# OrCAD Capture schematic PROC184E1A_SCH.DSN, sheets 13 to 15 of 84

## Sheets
13 13. SOC SERDES1 IF: size C; title: SERDES INTERFACE; company: TEXAS INSTRUMENTS INCORPORATED; note: PROC184_SCH
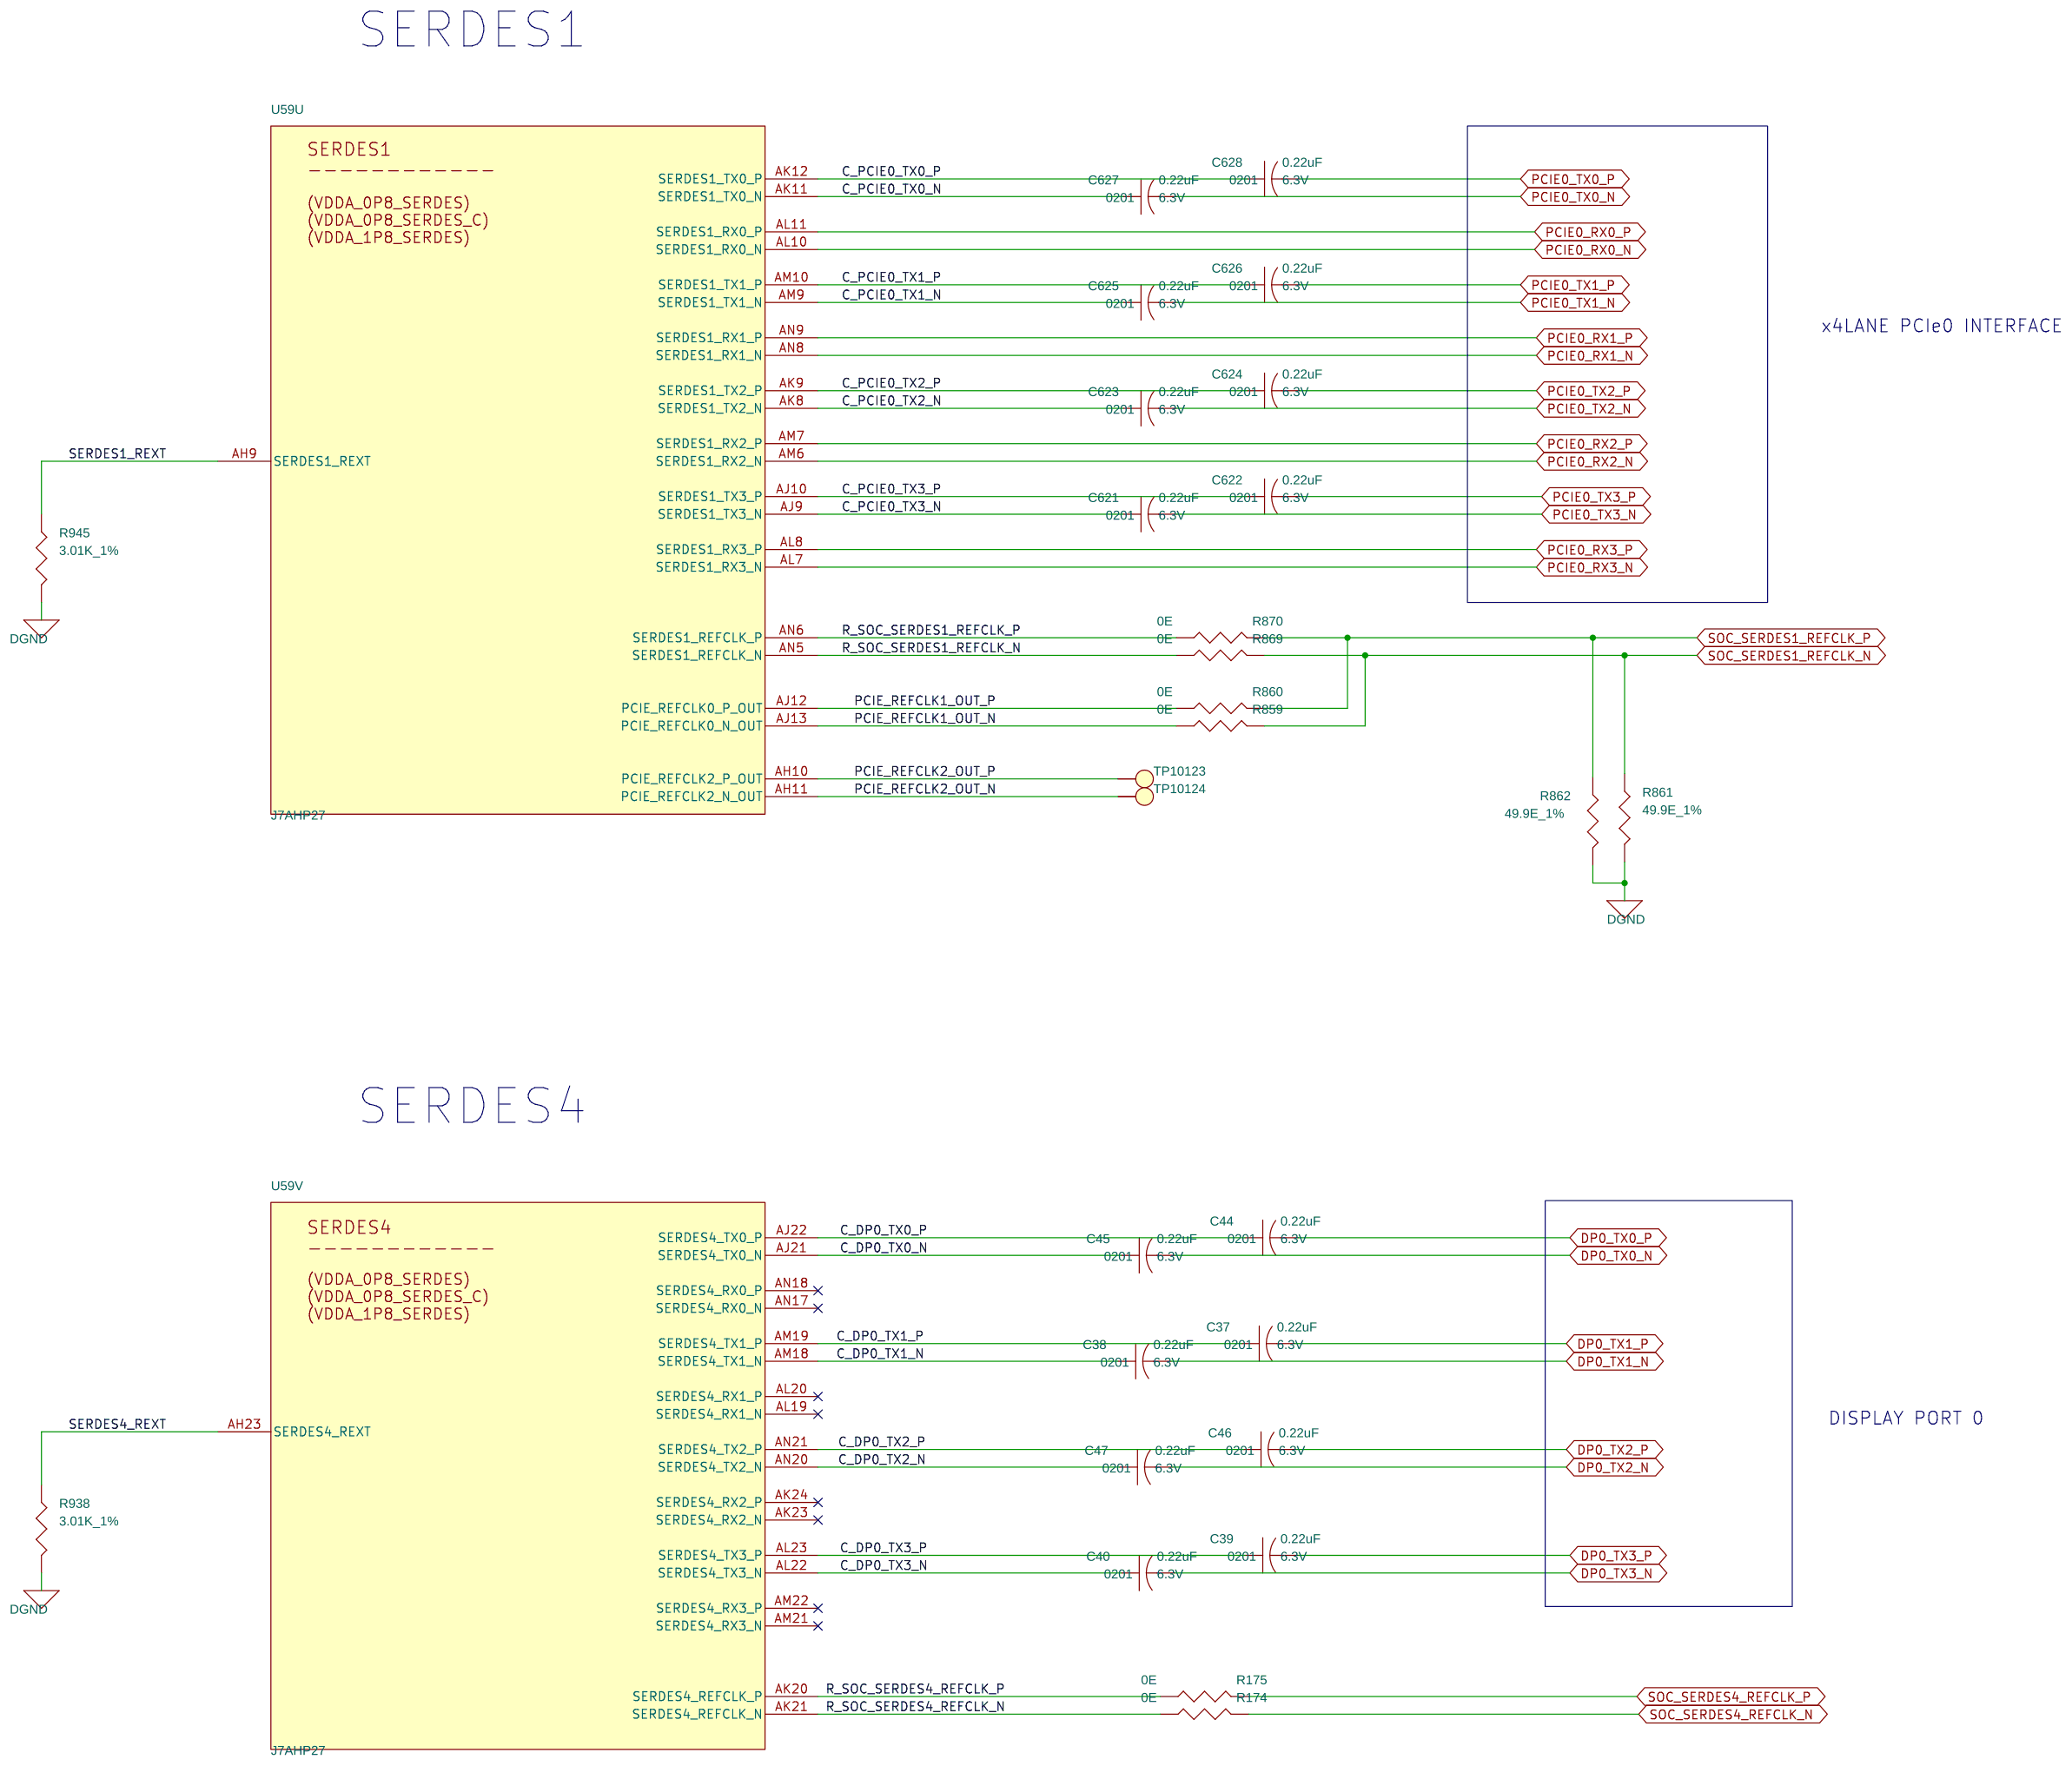
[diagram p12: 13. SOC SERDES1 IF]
14 14. SOC EMIF0 & LPDDR4: size C; title: EMIF0; company: TEXAS INSTRUMENTS INCORPORATED; note: PROC184_SCH
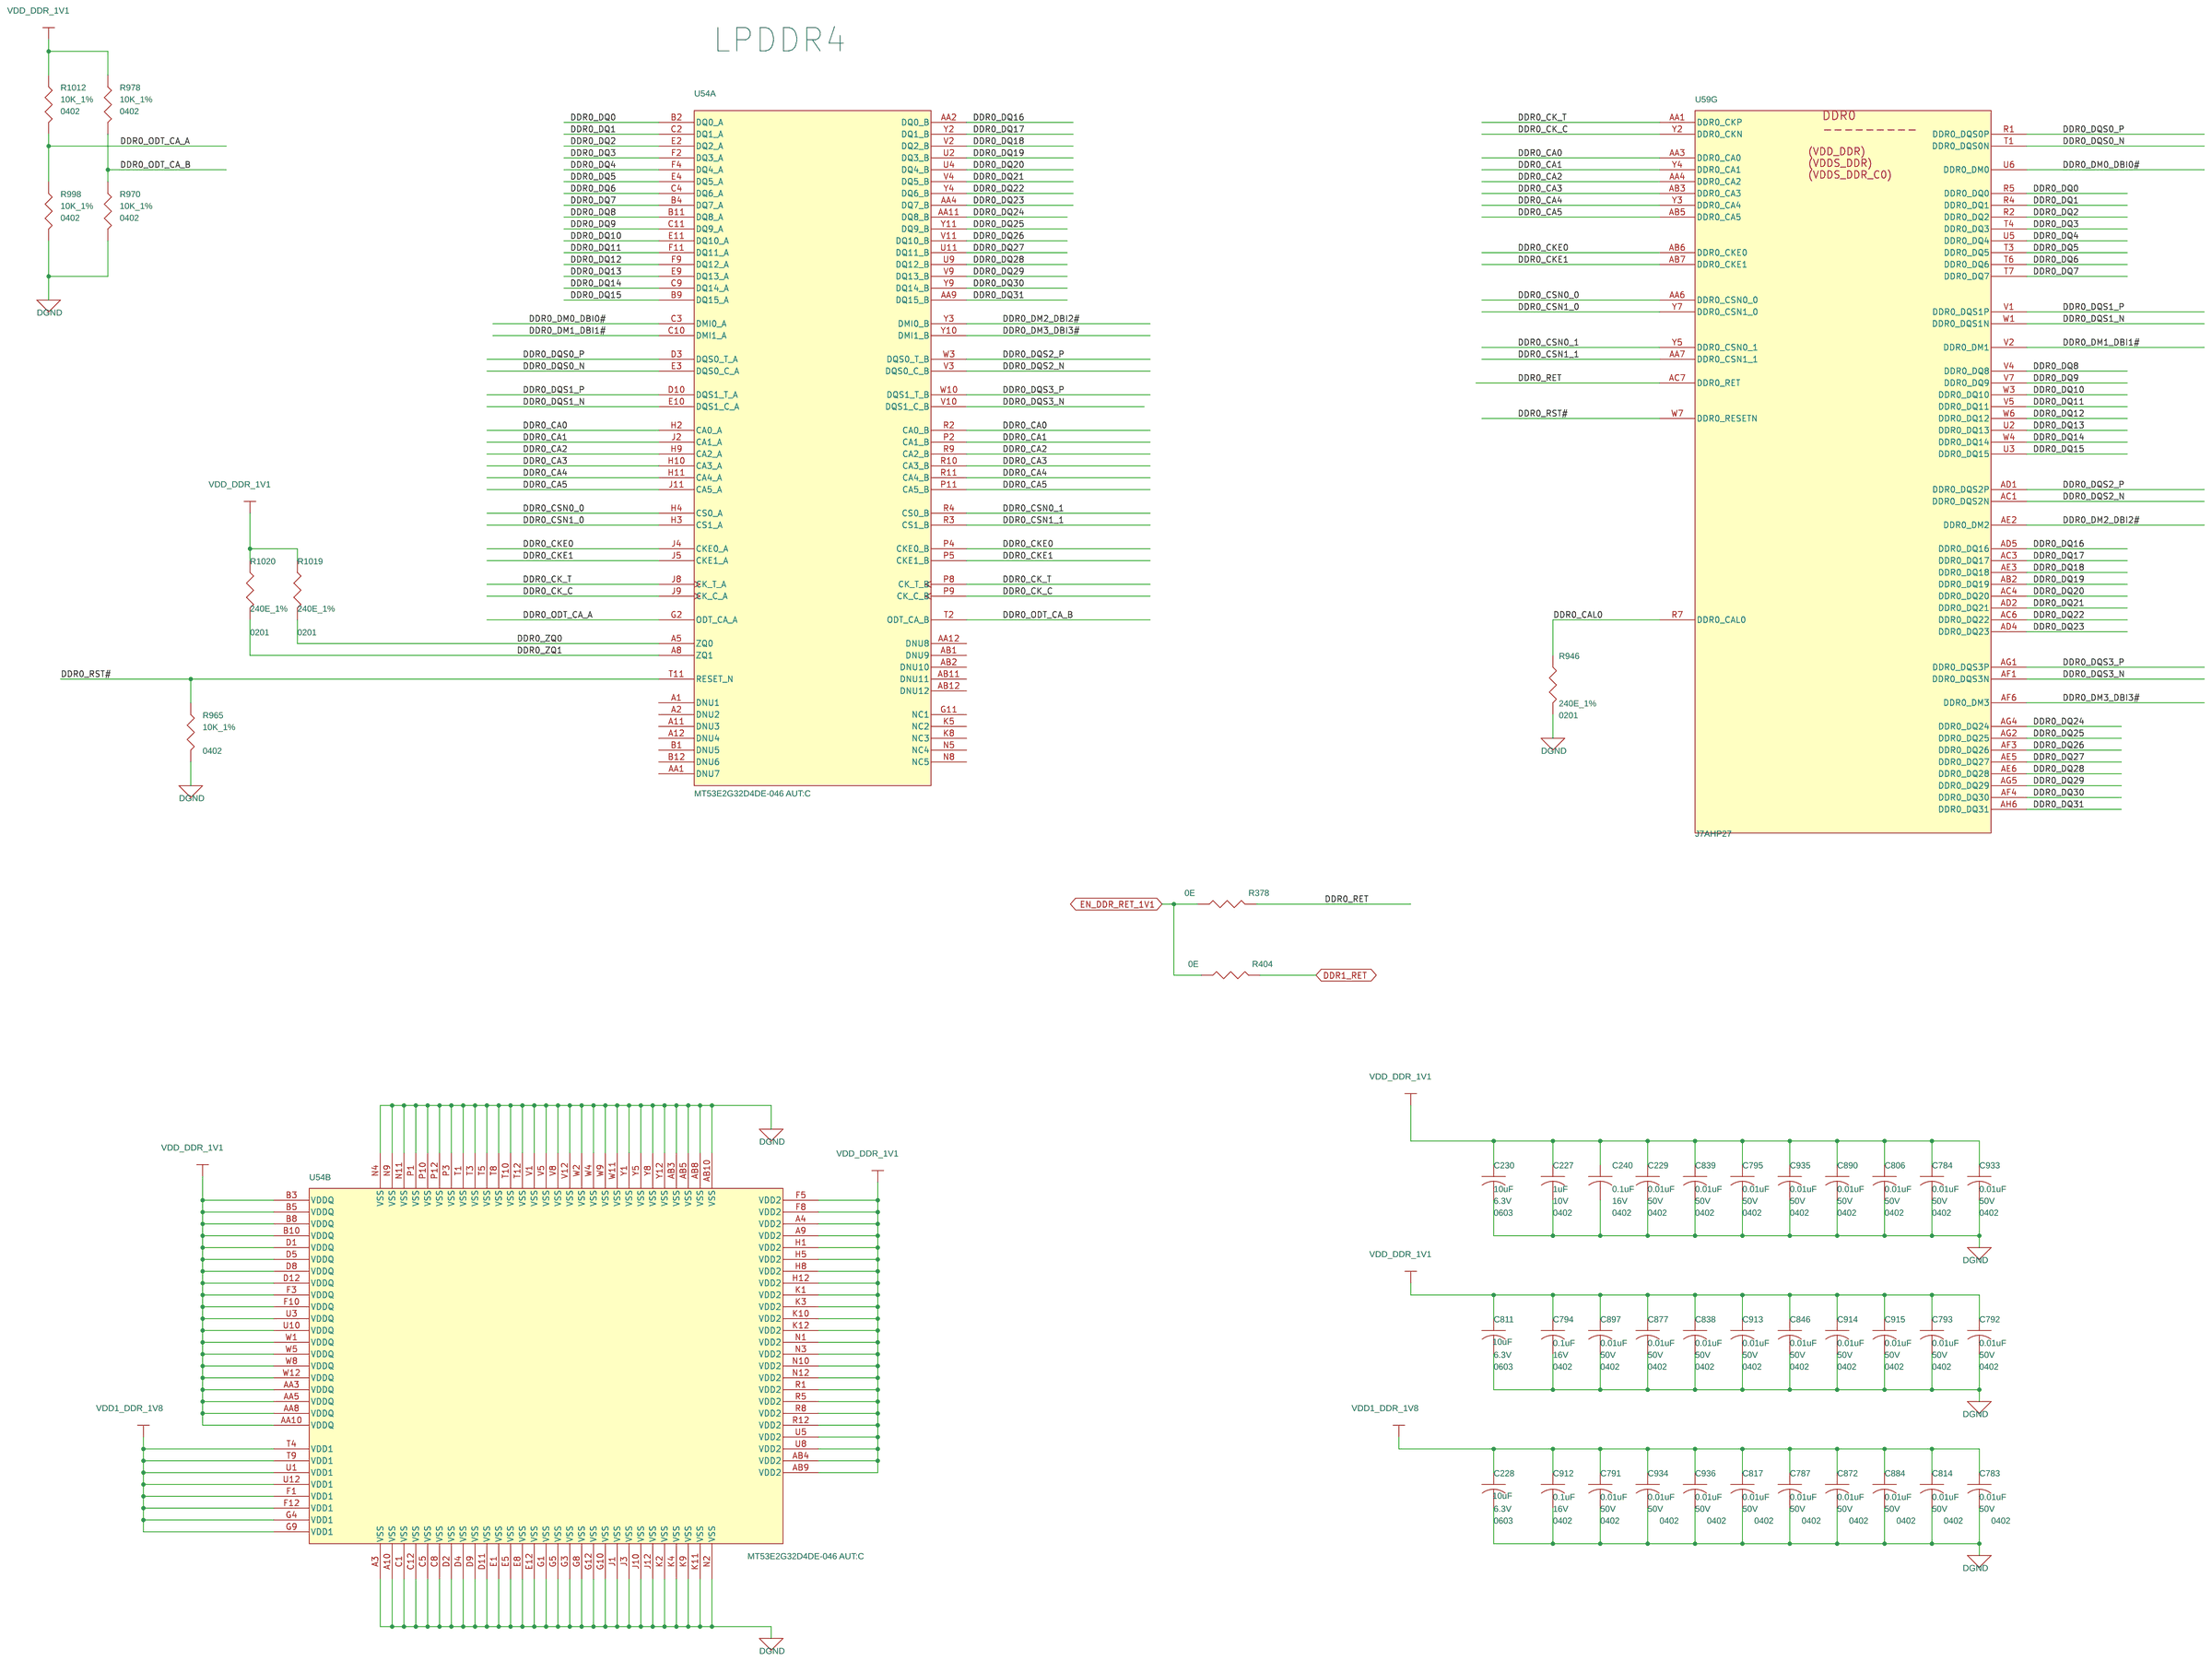
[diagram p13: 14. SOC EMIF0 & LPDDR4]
15 15. SOC EMIF1 & LPDDR4: size C; title: EMIF1; company: TEXAS INSTRUMENTS INCORPORATED; note: PROC184_SCH
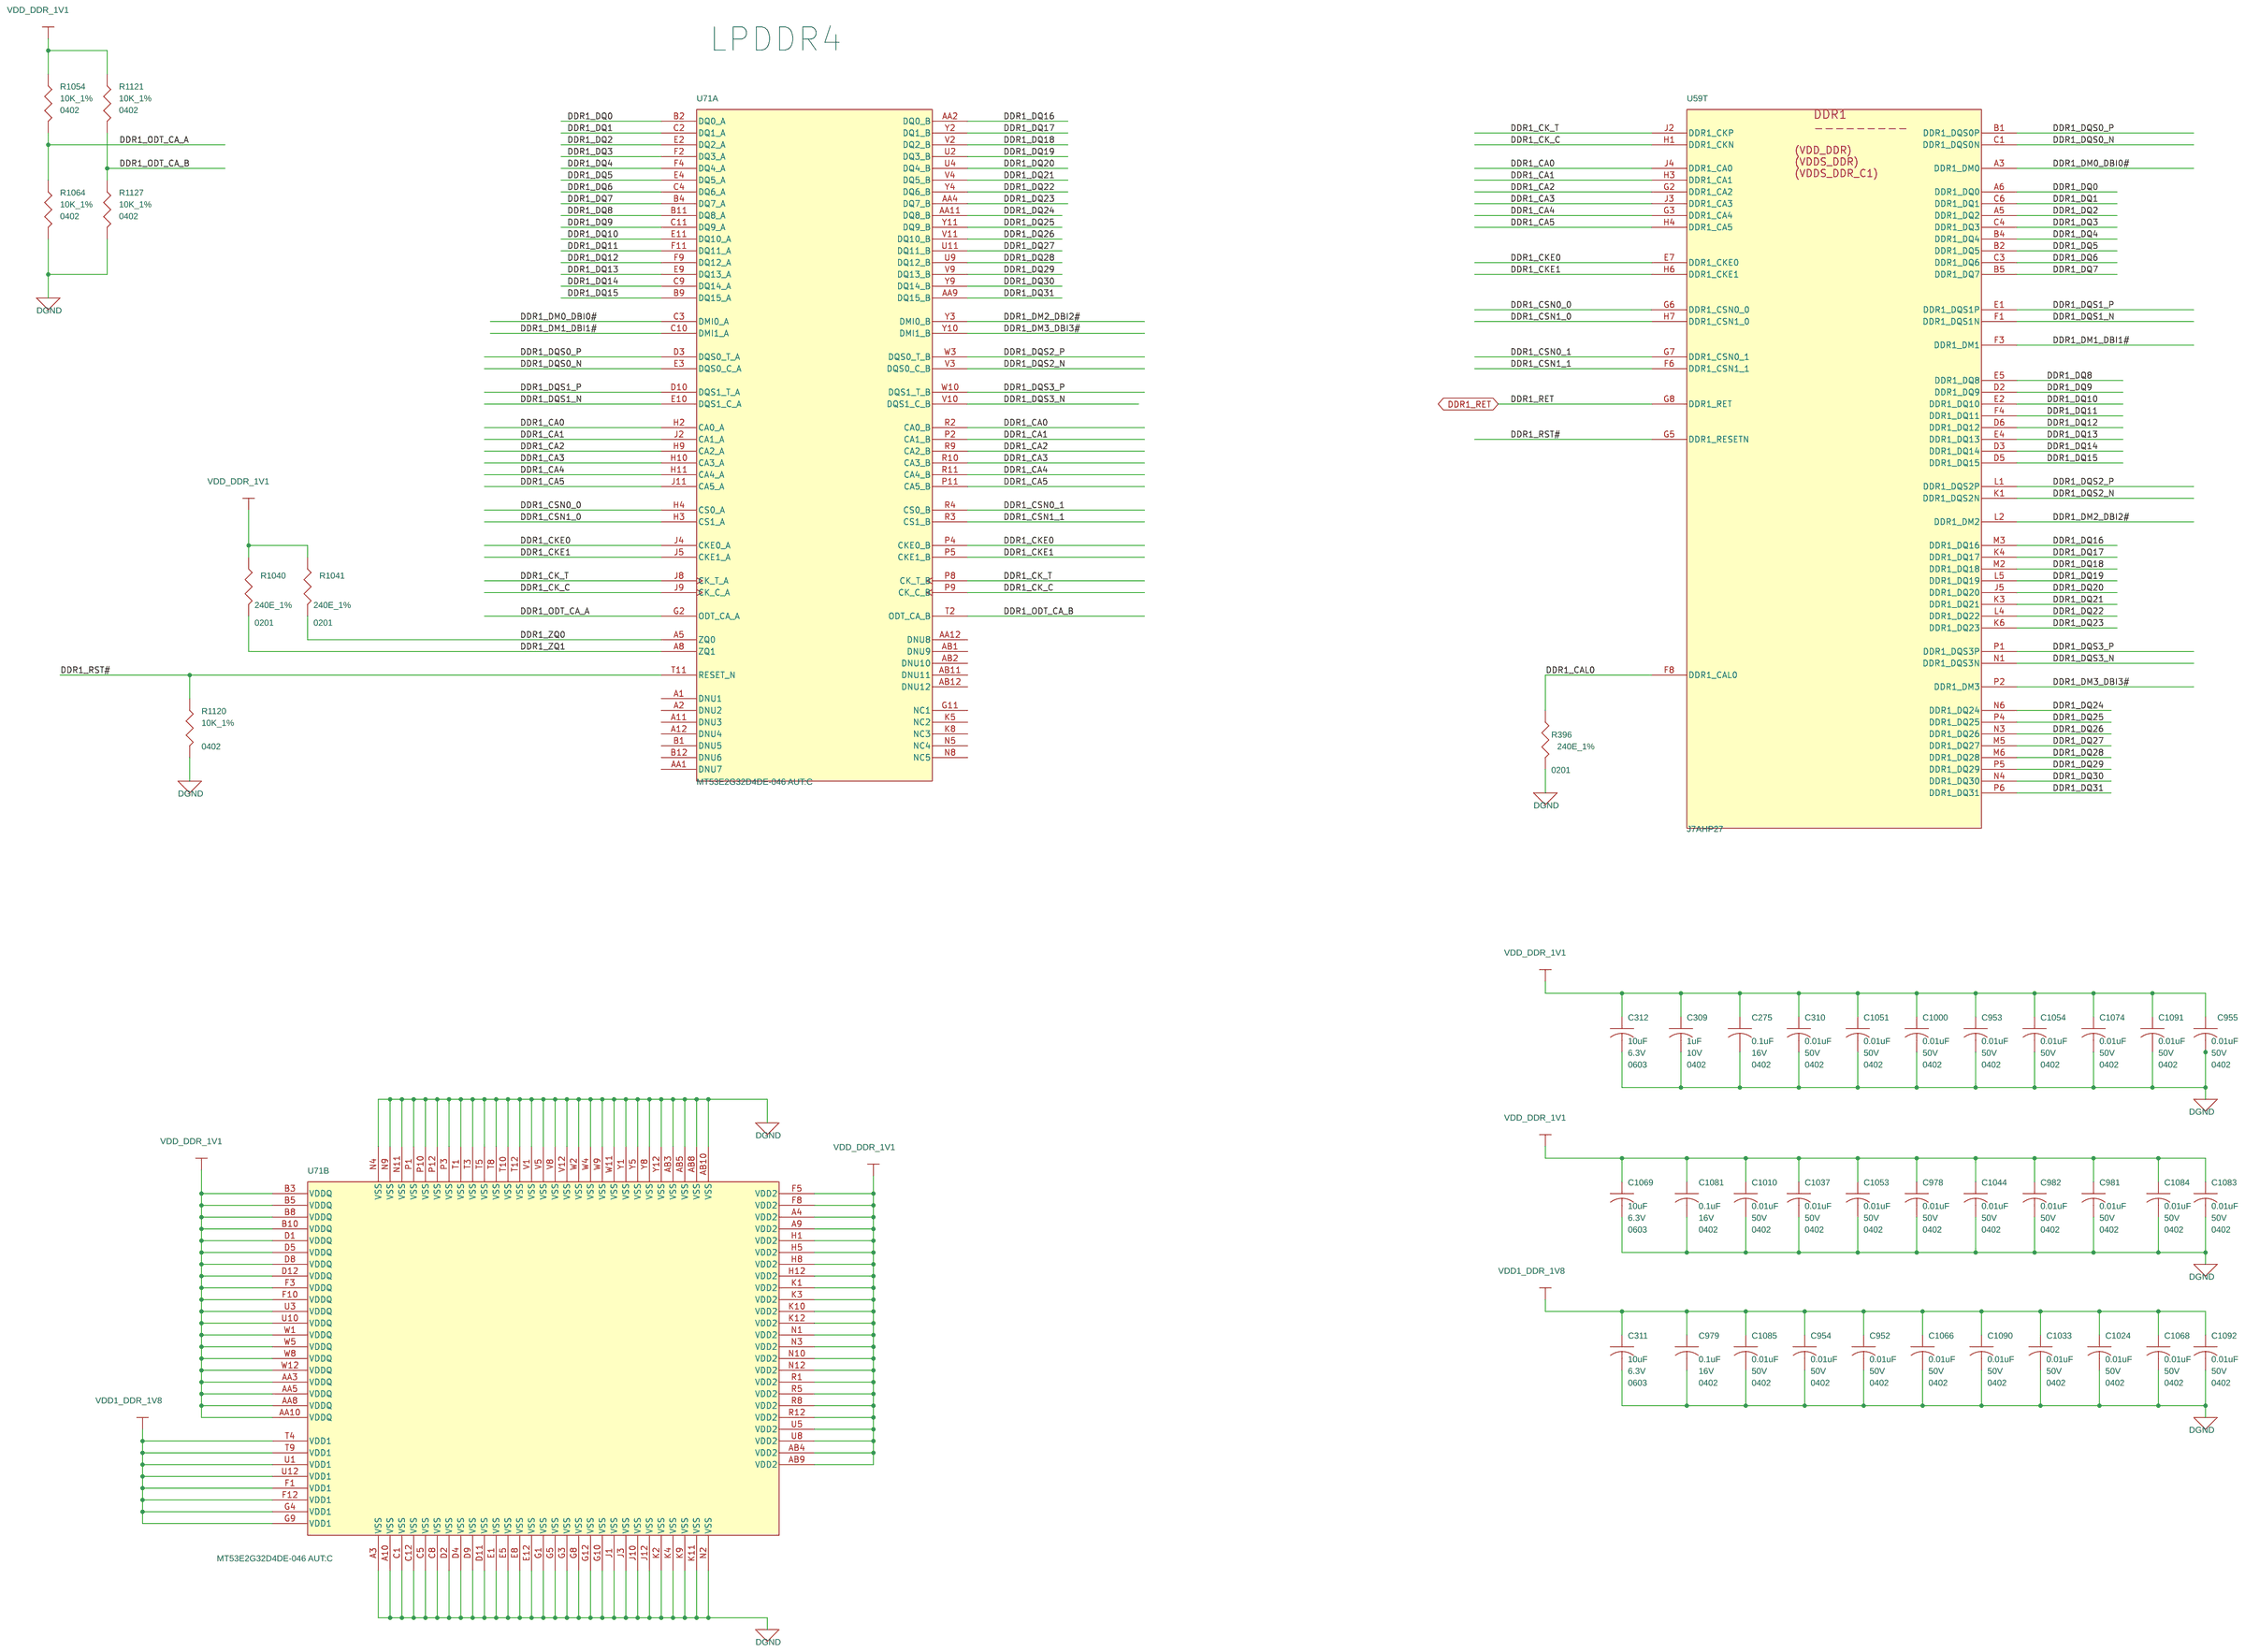
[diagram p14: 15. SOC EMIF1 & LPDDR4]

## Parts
sheet 13. SOC SERDES1 IF
C37  0.22uF  [CAP0201_0-5]
C38  0.22uF  [CAP0201_0-5]
C39  0.22uF  [CAP0201_0-5]
C40  0.22uF  [CAP0201_0-5]
C44  0.22uF  [CAP0201_0-5]
C45  0.22uF  [CAP0201_0-5]
C46  0.22uF  [CAP0201_0-5]
C47  0.22uF  [CAP0201_0-5]
C621  0.22uF  [CAP0201_0-5]
C622  0.22uF  [CAP0201_0-5]
C623  0.22uF  [CAP0201_0-5]
C624  0.22uF  [CAP0201_0-5]
C625  0.22uF  [CAP0201_0-5]
C626  0.22uF  [CAP0201_0-5]
C627  0.22uF  [CAP0201_0-5]
C628  0.22uF  [CAP0201_0-5]
R174  0E  [RES0201_0-5]
R175  0E  [RES0201_0-5]
R859  0E  [RES0201_0-5]
R860  0E  [RES0201_0-5]
R861  49.9E_1%  [RES0402_0-5]
R862  49.9E_1%  [RES0402_0-5]
R869  0E  [RES0201_0-5]
R870  0E  [RES0201_0-5]
R938  3.01K_1%  [RES0201_0-5]
R945  3.01K_1%  [RES0201_0-5]
TP10123  TP30_SMD  [TP30_SMD]
TP10124  TP30_SMD  [TP30_SMD]
sheet 14. SOC EMIF0 & LPDDR4
C227  1uF  [CAP0402_0-75]
C228  10uF  [CAP0603_1]
C229  0.01uF  [CAP0402_0-75]
C230  10uF  [CAP0603_1]
C240  0.1uF  [CAP0402_0-75]
C783  0.01uF  [CAP0402_0-75]
C784  0.01uF  [CAP0402_0-75]
C787  0.01uF  [CAP0402_0-75]
C791  0.01uF  [CAP0402_0-75]
C792  0.01uF  [CAP0402_0-75]
C793  0.01uF  [CAP0402_0-75]
C794  0.1uF  [CAP0402_0-75]
C795  0.01uF  [CAP0402_0-75]
C806  0.01uF  [CAP0402_0-75]
C811  10uF  [CAP0603_1]
C814  0.01uF  [CAP0402_0-75]
C817  0.01uF  [CAP0402_0-75]
C838  0.01uF  [CAP0402_0-75]
C839  0.01uF  [CAP0402_0-75]
C846  0.01uF  [CAP0402_0-75]
C872  0.01uF  [CAP0402_0-75]
C877  0.01uF  [CAP0402_0-75]
C884  0.01uF  [CAP0402_0-75]
C890  0.01uF  [CAP0402_0-75]
C897  0.01uF  [CAP0402_0-75]
C912  0.1uF  [CAP0402_0-75]
C913  0.01uF  [CAP0402_0-75]
C914  0.01uF  [CAP0402_0-75]
C915  0.01uF  [CAP0402_0-75]
C933  0.01uF  [CAP0402_0-75]
C934  0.01uF  [CAP0402_0-75]
C935  0.01uF  [CAP0402_0-75]
C936  0.01uF  [CAP0402_0-75]
R378  0E  [RES0201_0-5]
R404  0E  [RES0201_0-5]
R946  240E_1%  [RES0201_0-5]
R965  10K_1%  [RES0402_0-5]
R970  10K_1%  [RES0402_0-5]
R978  10K_1%  [RES0402_0-5]
R998  10K_1%  [RES0402_0-5]
R1012  10K_1%  [RES0402_0-5]
R1019  240E_1%  [RES0201_0-5]
R1020  240E_1%  [RES0201_0-5]
U54  MT53E2G32D4DE-046 AUT:C  [WFBGA200_MT53DDS_400X570_1-2]  (sections A,B)
sheet 15. SOC EMIF1 & LPDDR4
C275  0.1uF  [CAP0402_0-75]
C309  1uF  [CAP0402_0-75]
C310  0.01uF  [CAP0402_0-75]
C311  10uF  [CAP0603_1]
C312  10uF  [CAP0603_1]
C952  0.01uF  [CAP0402_0-75]
C953  0.01uF  [CAP0402_0-75]
C954  0.01uF  [CAP0402_0-75]
C955  0.01uF  [CAP0402_0-75]
C978  0.01uF  [CAP0402_0-75]
C979  0.1uF  [CAP0402_0-75]
C981  0.01uF  [CAP0402_0-75]
C982  0.01uF  [CAP0402_0-75]
C1000  0.01uF  [CAP0402_0-75]
C1010  0.01uF  [CAP0402_0-75]
C1024  0.01uF  [CAP0402_0-75]
C1033  0.01uF  [CAP0402_0-75]
C1037  0.01uF  [CAP0402_0-75]
C1044  0.01uF  [CAP0402_0-75]
C1051  0.01uF  [CAP0402_0-75]
C1053  0.01uF  [CAP0402_0-75]
C1054  0.01uF  [CAP0402_0-75]
C1066  0.01uF  [CAP0402_0-75]
C1068  0.01uF  [CAP0402_0-75]
C1069  10uF  [CAP0603_1]
C1074  0.01uF  [CAP0402_0-75]
C1081  0.1uF  [CAP0402_0-75]
C1083  0.01uF  [CAP0402_0-75]
C1084  0.01uF  [CAP0402_0-75]
C1085  0.01uF  [CAP0402_0-75]
C1090  0.01uF  [CAP0402_0-75]
C1091  0.01uF  [CAP0402_0-75]
C1092  0.01uF  [CAP0402_0-75]
R396  240E_1%  [RES0201_0-5]
R1040  240E_1%  [RES0201_0-5]
R1041  240E_1%  [RES0201_0-5]
R1054  10K_1%  [RES0402_0-5]
R1064  10K_1%  [RES0402_0-5]
R1120  10K_1%  [RES0402_0-5]
R1121  10K_1%  [RES0402_0-5]
R1127  10K_1%  [RES0402_0-5]
U59  J7AHP27  [BGASKT-33X33-1063-P8MM]  (sections A,B,C,D,E,F,G,H,I,J,K,L,M,N,O,P,Q,R,S,T,U,V,W)
U71  MT53E2G32D4DE-046 AUT:C  [WFBGA200_MT53DDS_400X570_1-2]  (sections A,B)

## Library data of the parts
C37-C40 C44-C47 C621-C628 = CAP: CAP CERAMIC 0.22uF 6.3V 10% X6S AUTO 0201; Chkd/date: MANIRAJA/220219; Crtd /date: ALVY/220219; Custom_Duty: 15%; Customs_HS_Code: 85322990; Distributor_name: DIGIKEY; Distributor_part_number: 490-12230-1-ND; Footprint Path: Y:\MIS_DATABASE\Library\ALTIUM_TOOL\PCB_FOOTPRINTS\Altium_Footprint_Lib.PcbLib; Height: 0.33MM; Library Path: Y:\MIS_DATABASE\Library\ALTIUM_TOOL\SCHEMATICS_PARTS\MS_DISCRETE_Library.schlib; Manufacturer: MURATA; Mfr_name: MURATA; Mfr_part_number: GRT033C80J224KE01D; Mistral Part No: 120019020011-R; Package: 0201; Part_type: CAPACITORS\CERAMIC; Project: TI_J7ES_EVM_SOM; RoHS: RoHS; Temperature: -55°C+105°C; Tolerance: 10%; Voltage: 6.3V; Wattage: NA; Weight: 0.17mg; Datasheet: Y:\MIS_DATABASE\DATASHEETS\CAPACITORS\MURATA-GCM-SER.PDF
R174 R175 R378 R404 R859 R860 R869 R870 = RESISTOR: RES 0E 1/20W 5% 0201; Chkd/date: NAVEED/301214; Crtd /date: MUDDU/120710; Custom_Duty: 15%; Customs_HS_Code: 85332119; Distributor_name: DIGIKEY; Distributor_part_number: 311-0.0NCT-ND; Footprint Path: Y:\MIS_DATABASE\Library\ALTIUM_TOOL\PCB_FOOTPRINTS\Altium_Footprint_Lib.PcbLib; Height: 0.26MM; Library Path: Y:\MIS_DATABASE\Library\ALTIUM_TOOL\SCHEMATICS_PARTS\MS_DISCRETE_Library.schlib; Manufacturer: YAGEO AMERICA; Mfr_name: YAGEO AMERICA; Mfr_part_number: RC0201JR-070RL; Mistral Part No: 110010070067-R; Package: 0201; Part_type: RESISTORS\FIXED; Project: PB_BUGBASE; RoHS: RoHS; Temperature: -55°C+125°C; Tolerance: 5%; Voltage: NA; Wattage: 1/20W; Weight: 0.17mg; Datasheet: Y:\MIS_DATABASE\DATASHEETS\RESISTORS\RCXXXXL-SER_MAR18.PDF
R861 R862 = RESISTOR: RES 49.9E 1/10W 1% 0402; Chkd/date: VASANTHA/201216; Crtd /date: MAZHAR/201005; Custom_Duty: 15%; Customs_HS_Code: 85332119; Distributor_name: DIGIKEY; Distributor_part_number: P49.9LCT-ND; Footprint Path: Y:\MIS_DATABASE\Library\ALTIUM_TOOL\PCB_FOOTPRINTS\Altium_Footprint_Lib.PcbLib; Height: 0.40MM; Library Path: Y:\MIS_DATABASE\Library\ALTIUM_TOOL\SCHEMATICS_PARTS\MS_DISCRETE_Library.schlib; Manufacturer: PANASONIC-ECG; Mfr_name: PANASONIC-ECG; Mfr_part_number: ERJ-2RKF49R9X; Mistral Part No: 110009030897-R; Package: 0402; Part_type: RESISTORS\FIXED; Project: RED EYE; RoHS: RoHS; Temperature: -55°C+155°C; Tolerance: 1%; Voltage: NA; Wattage: 1/10W; Weight: 0.8mg; Datasheet: Y:\MIS_DATABASE\DATASHEETS\RESISTORS\PAN-ERJSER_NOV17.PDF
R938 R945 = RESISTOR: RES 3.01K 1/20W 1% 0201; Chkd/date: MANIRAJA/160519; Crtd /date: ALVY/160519; Custom_Duty: 15%; Customs_HS_Code: 85332119; Distributor_name: DIGIKEY; Distributor_part_number: P122916CT-ND; Footprint Path: Y:\MIS_DATABASE\Library\ALTIUM_TOOL\PCB_FOOTPRINTS\Altium_Footprint_Lib.PcbLib; Height: 0.26MM; Library Path: Y:\MIS_DATABASE\Library\ALTIUM_TOOL\SCHEMATICS_PARTS\MS_DISCRETE_Library.schlib; Manufacturer: PANASONIC-ECG; Mfr_name: PANASONIC-ECG; Mfr_part_number: ERJ-1GNF3011C; Mistral Part No: 110015080044-R; Package: 0201; Part_type: RESISTORS\FIXED; Project: J7ES_SOM_DUAL-LEO_PMIC; RoHS: RoHS; Temperature: -55°C+125°C; Tolerance: 1%; Voltage: NA; Wattage: 1/20W; Weight: 0.15mg; Datasheet: Y:\MIS_DATABASE\DATASHEETS\RESISTORS\PAN-ERJSER_NOV17.PDF
TP10123 TP10124 = TESTPOINT: TESTPOINT CIR 30 SMD; Chkd/date: SHREESHAIL/171006; Crtd /date: MAZHAR/171006; Custom_Duty: NA; Customs_HS_Code: NA; Distributor_name: NA; Distributor_part_number: NA; Footprint Path: Y:\MIS_DATABASE\Library\ALTIUM_TOOL\PCB_FOOTPRINTS\Altium_Footprint_Lib.PcbLib; Height: NA; Library Path: Y:\MIS_DATABASE\Library\ALTIUM_TOOL\SCHEMATICS_PARTS\MS_DISCRETE_Library.schlib; MECHANICAL 3D STEP FILE: NA; Manufacturer: LOCAL; Mfr_name: LOCAL; Mistral Part No: 130009030930; Package: SMD; Project: BT MODULE_CSRBC04; RoHS: NA; Temperature: NA; Tolerance: NA; Voltage: NA; Wattage: NA; Weight: NA; Datasheet: NA
C227 C309 = CAP: CAP CERAMIC 1uF 10V 10% X7S AUTO 0402; Chkd/date: MANIRAJA/100918; Crtd /date: ALVY/100918; Custom_Duty: 15%; Customs_HS_Code: 85322990; Distributor_name: DIGIKEY; Distributor_part_number: 490-13409-1-ND; Footprint Path: Y:\MIS_DATABASE\Library\ALTIUM_TOOL\PCB_FOOTPRINTS\Altium_Footprint_Lib.PcbLib; Height: 0.70MM; Library Path: Y:\MIS_DATABASE\Library\ALTIUM_TOOL\SCHEMATICS_PARTS\MS_DISCRETE_Library.schlib; Manufacturer: MURATA; Mfr_name: MURATA; Mfr_part_number: GCM155C71A105KE38D; Mistral Part No: 120018090021-R; Package: 0402; Part_type: CAPACITORS\CERAMIC; Project: SMART-M_SCRIPTALK_PB; RoHS: RoHS; Temperature: -55°C+125°C; Tolerance: 10%; Voltage: 10V; Wattage: NA; Weight: 6mg; Datasheet: Y:\MIS_DATABASE\DATASHEETS\CAPACITORS\MURATA-GCM-SER.PDF
C228 C230 C311 C312 C811 C1069 = CAP: CAP CERAMIC 10uF 6.3V 20% X7T AUTO 0603; Automotive Alternate_mfr_name: MURATA; Automotive Alternate_mfr_part_number: GRT188C81C106ME13D; Chkd/date: MANIRAJA/120520; Crtd /date: ALVY/110520; Custom_Duty: 15%; Customs_HS_Code: 85322990; Direct Alternate_mfr_name: SAMSUNG; Direct Alternate_mfr_part_number: CL10X106MO8NRNC; Distributor_name: MOUSER; Distributor_part_number: 81-GCM188D70J106ME6D; Footprint Path: Y:\MIS_DATABASE\Library\ALTIUM_TOOL\PCB_FOOTPRINTS\Altium_Footprint_Lib.PcbLib; Height: 1.00MM; Library Path: Y:\MIS_DATABASE\Library\ALTIUM_TOOL\SCHEMATICS_PARTS\MS_DISCRETE_Library.schlib; Manufacturer: MURATA; Mfr_name: MURATA; Mfr_part_number: GCM188D70J106ME36D; Mistral Part No: 120020050003-R; Package: 0603; Part_type: CAPACITORS\CERAMIC; Project: J7VCL_SOM_LEO_HERA PMIC BRD; RoHS: RoHS; Temperature: -55°C+125°C; Tolerance: 20%; Voltage: 6.3V; Wattage: NA; Weight: 6.3mg; Datasheet: Y:\MIS_DATABASE\DATASHEETS\CAPACITORS\GCM188D70J106ME36.PDF
C229 C310 C783 C784 C787 C791-C793 C795 C806 C814 C817 C838 C839 C846 C872 C877 C884 C890 C897 C913-C915 C933-C936 C952-C955 C978 C981 C982 C1000 C1010 C1024 C1033 C1037 C1044 C1051 C1053 C1054 C1066 C1068 C1074 C1083-C1085 C1090-C1092 = CAP: CAP CERAMIC 0.01uF 50V 10% X7R 0402; Automotive Alternate_mfr_name: TDK; Automotive Alternate_mfr_part_number: CGA2B3X7R1H103K050BB; Chkd/date: MANIRAJA/280319; Crtd /date: MANIRAJA/280319; Custom_Duty: 15%; Customs_HS_Code: 85322990; Direct Alternate_mfr_name: TDK; Direct Alternate_mfr_part_number: C1005X7R1H103K050BE; Distributor_name: DIGIKEY; Distributor_part_number: 490-4516-1-ND; Footprint Path: Y:\MIS_DATABASE\Library\ALTIUM_TOOL\PCB_FOOTPRINTS\Altium_Footprint_Lib.PcbLib; Height: 0.55MM; Library Path: Y:\MIS_DATABASE\Library\ALTIUM_TOOL\SCHEMATICS_PARTS\MS_DISCRETE_Library.schlib; Manufacturer: MURATA; Mfr_name: MURATA; Mfr_part_number: GRM155R71H103KA88D; Mistral Part No: 120009030025-R; Package: 0402; Part_type: CAPACITORS\CERAMIC; Project: G4_SVGA; RoHS: RoHS; Temperature: -55°C+125°C; Tolerance: 10%; Voltage: 50V; Wattage: NA; Weight: 0.65mg; Datasheet: Y:\MIS_DATABASE\DATASHEETS\CAPACITORS\GRM155R71H103KA88D.PDF
C240 C275 C794 C912 C979 C1081 = CAP: CAP CERAMIC 0.1uF 16V 10% X7R AUTO 0402; Automotive Alternate_mfr_name: TDK; Automotive Alternate_mfr_part_number: CGA2B1X7R1C104K050BC; Chkd/date: NAVEED/021014; Crtd /date: VASANTHA/300514; Custom_Duty: 15%; Customs_HS_Code: 85322990; Direct Alternate_mfr_name: TDK; Direct Alternate_mfr_part_number: CGA2B1X7R1C104K050BC; Distributor_name: DIGIKEY; Distributor_part_number: 490-4759-1-ND; Footprint Path: Y:\MIS_DATABASE\Library\ALTIUM_TOOL\PCB_FOOTPRINTS\Altium_Footprint_Lib.PcbLib; Height: 0.55MM; Library Path: Y:\MIS_DATABASE\Library\ALTIUM_TOOL\SCHEMATICS_PARTS\MS_DISCRETE_Library.schlib; Manufacturer: MURATA; Mfr_name: MURATA; Mfr_part_number: GCM155R71C104KA55D; Mistral Part No: 120016070006-R; Package: 0402; Part_type: CAPACITORS\CERAMIC; Project: DCMIST_FPGA_CARD; RoHS: RoHS; Temperature: -55°C+125°C; Tolerance: 10%; Voltage: 16V; Wattage: NA; Weight: 6mg; Datasheet: Y:\MIS_DATABASE\DATASHEETS\CAPACITORS\MURATA-GCM-SER.PDF
R396 R946 = RESISTOR: RES 240E 1/20W 1% 0201; Chkd/date: VASANTHA/251116; Crtd /date: MANIRAJA/241116; Custom_Duty: 15%; Customs_HS_Code: 85332119; Distributor_name: DIGIKEY; Distributor_part_number: YAG2528CT-ND; Footprint Path: Y:\MIS_DATABASE\Library\ALTIUM_TOOL\PCB_FOOTPRINTS\Altium_Footprint_Lib.PcbLib; Height: 0.26MM; Library Path: Y:\MIS_DATABASE\Library\ALTIUM_TOOL\SCHEMATICS_PARTS\MS_DISCRETE_Library.schlib; Manufacturer: YAGEO AMERICA; Mfr_name: YAGEO AMERICA; Mfr_part_number: RC0201FR-07240RL; Mistral Part No: 110016110007-R; Package: 0201; Part #: 103413-2401R; Part_type: RESISTORS\FIXED; Project: ALL_DATA_NANO_SOM; RoHS: RoHS; Temperature: -55°C+125°C; Tolerance: 1%; Voltage: NA; Wattage: 1/20W; Weight: 0.17mg; Datasheet: Y:\MIS_DATABASE\DATASHEETS\RESISTORS\RCXXXXL-SER_MAR18.PDF
R965 R970 R998 R1064 R1120 R1127 = RESISTOR: RES 10K 1/16W 1% 0402; Assembly_Instruction: DNI; Chkd/date: VASANTHA/201216; Crtd /date: GEETHA/290506; Custom_Duty: 15%; Customs_HS_Code: 85332119; Distributor_name: DIGIKEY; Distributor_part_number: 311-10.0KLRTR-ND; Footprint Path: Y:\MIS_DATABASE\Library\ALTIUM_TOOL\PCB_FOOTPRINTS\Altium_Footprint_Lib.PcbLib; Height: 0.40MM; Library Path: Y:\MIS_DATABASE\Library\ALTIUM_TOOL\SCHEMATICS_PARTS\MS_DISCRETE_Library.schlib; Manufacturer: YAGEO AMERICA; Mfr_name: YAGEO AMERICA; Mfr_part_number: RC0402FR-0710KL; Mistral Part No: 110015090015-R; Package: 0402; Part_type: RESISTORS\FIXED; Project: VOCERA; RoHS: RoHS; Temperature: -55°C+155°C; Tolerance: 1%; Voltage: NA; Wattage: 1/16W; Weight: 0.65mg; Datasheet: Y:\MIS_DATABASE\DATASHEETS\RESISTORS\RCXXXXL-SER_MAR18.PDF
R978 R1012 R1054 R1121 = RESISTOR: RES 10K 1/16W 1% 0402; Chkd/date: VASANTHA/201216; Crtd /date: GEETHA/290506; Custom_Duty: 15%; Customs_HS_Code: 85332119; Distributor_name: DIGIKEY; Distributor_part_number: 311-10.0KLRTR-ND; Footprint Path: Y:\MIS_DATABASE\Library\ALTIUM_TOOL\PCB_FOOTPRINTS\Altium_Footprint_Lib.PcbLib; Height: 0.40MM; Library Path: Y:\MIS_DATABASE\Library\ALTIUM_TOOL\SCHEMATICS_PARTS\MS_DISCRETE_Library.schlib; Manufacturer: YAGEO AMERICA; Mfr_name: YAGEO AMERICA; Mfr_part_number: RC0402FR-0710KL; Mistral Part No: 110015090015-R; Package: 0402; Part_type: RESISTORS\FIXED; Project: VOCERA; RoHS: RoHS; Temperature: -55°C+155°C; Tolerance: 1%; Voltage: NA; Wattage: 1/16W; Weight: 0.65mg; Datasheet: Y:\MIS_DATABASE\DATASHEETS\RESISTORS\RCXXXXL-SER_MAR18.PDF
R1019 R1020 R1040 R1041 = RESISTOR: RES 240E 1/20W 1% 0201; Chkd/date: VASANTHA/251116; Crtd /date: MANIRAJA/241116; Custom_Duty: 15%; Customs_HS_Code: 85332119; Distributor_name: DIGIKEY; Distributor_part_number: YAG2528CT-ND; Footprint Path: Y:\MIS_DATABASE\Library\ALTIUM_TOOL\PCB_FOOTPRINTS\Altium_Footprint_Lib.PcbLib; Height: 0.26MM; Library Path: Y:\MIS_DATABASE\Library\ALTIUM_TOOL\SCHEMATICS_PARTS\MS_DISCRETE_Library.schlib; Manufacturer: YAGEO AMERICA; Mfr_name: YAGEO AMERICA; Mfr_part_number: RC0201FR-07240RL; Mistral Part No: 110016110007-R; Package: 0201; Part_type: RESISTORS\FIXED; Project: ALL_DATA_NANO_SOM; RoHS: RoHS; Temperature: -55°C+125°C; Tolerance: 1%; Voltage: NA; Wattage: 1/20W; Weight: 0.17mg; Datasheet: Y:\MIS_DATABASE\DATASHEETS\RESISTORS\RCXXXXL-SER_MAR18.PDF
U54 U71 = MT53D1024M32D4DT_VFBGA200: IC 8Gb AUTO LPDDR4/LPDDR4x SDRAM TFBGA200; Chkd/date: ALVY/170122; Crtd /date: MANIRAJA/170122; Custom_Duty: 15%; Customs_HS_Code: 85423100; Distributor_name: NA; Distributor_part_number: NA; Footprint Path: Y:\MIS_DATABASE\Library\ALTIUM_TOOL\PCB_FOOTPRINTS\Altium_Footprint_Lib.PcbLib; Height: 1.14MM; Library Path: Y:\MIS_DATABASE\Library\ALTIUM_TOOL\SCHEMATICS_PARTS\MS_MISCMEMORY_Library.schlib; Manufacturer: MICRON; Mfr_name: MICRON; Mistral Part No: 141122010003-R; Package: TFBGA200; Part_type: ICS\DIGITAL\MEMORY; Project: J7AHP_PROTO_BRD; RoHS: RoHS; Temperature: -40°C+125°C; Tolerance: NA; Voltage: NA; Wattage: NA; Weight: NA; Datasheet: Y:\MIS_DATABASE\DATASHEETS\ICS\MEMORY\MT53EX-C-AUTO.PDF
U59 = J7AHP27SoC_BGA1063: IC J7AHP27 SoC EVM MICROPROCESSOR BGA1063; Chkd/date: PRADEEP/181223; Crtd /date: TAMILARASU/111223; Custom_Duty: 15%; Customs_HS_Code: 85423100; Distributor_name: NA; Distributor_part_number: NA; Footprint Path: Y:\MIS_DATABASE\Library\ALTIUM_TOOL\PCB_FOOTPRINTS\Altium_Footprint_Lib.PcbLib; Height: 3.30MM; Library Path: Y:\MIS_DATABASE\Library\ALTIUM_TOOL\SCHEMATICS_PARTS\MS_MICROPROCESSOR_Library.schlib; Mfr_name: NA; Mistral Part No: 141223120002; Package: BGA1063; Part_type: ICS\DIGITAL\MICROPROCESSOR; Project: J7AHP27_V08 SOC; RoHS: NA; Temperature: NA; Tolerance: NA; Voltage: NA; Wattage: NA; Weight: NA; Datasheet: Y:\MIS_DATABASE\DATASHEETS\ICS\DIGITAL\MICROCONTROLLER\J7AHP27.PDF

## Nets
DGND: C227.2 C228.2 C229.2 C230.2 C240.2 C275.2 C309.2 C310.2 C311.2 C312.2 C783.2 C784.2 C787.2 C791.2 C792.2 C793.2 C794.2 C795.2 C806.2 C811.2 C814.2 C817.2 C838.2 C839.2 C846.2 C872.2 C877.2 C884.2 C890.2 C897.2 C912.2 C913.2 C914.2 C915.2 C933.2 C934.2 C935.2 C936.2 C952.2 C953.2 C954.2 C955.2 C978.2 C979.2 C981.2 C982.2 C1000.2 C1010.2 C1024.2 C1033.2 C1037.2 C1044.2 C1051.2 C1053.2 C1054.2 C1066.2 C1068.2 C1069.2 C1074.2 C1081.2 C1083.2 C1084.2 C1085.2 C1090.2 C1091.2 C1092.2 R396.2 R861.2 R862.2 R938.2 R945.2 R946.2 R965.2 R970.2 R998.2 R1064.2 R1120.2 R1127.2 U54.A3(VSS) U54.A10(VSS) U54.AB3(VSS) U54.AB5(VSS) U54.AB8(VSS) U54.AB10(VSS) U54.C1(VSS) U54.C5(VSS) U54.C8(VSS) U54.C12(VSS) U54.D2(VSS) U54.D4(VSS) U54.D9(VSS) U54.D11(VSS) U54.E1(VSS) U54.E5(VSS) U54.E8(VSS) U54.E12(VSS) U54.G1(VSS) U54.G3(VSS) U54.G5(VSS) U54.G8(VSS) U54.G10(VSS) U54.G12(VSS) U54.J1(VSS) U54.J3(VSS) U54.J10(VSS) U54.J12(VSS) U54.K2(VSS) U54.K4(VSS) U54.K9(VSS) U54.K11(VSS) U54.N2(VSS) U54.N4(VSS) U54.N9(VSS) U54.N11(VSS) U54.P1(VSS) U54.P3(VSS) U54.P10(VSS) U54.P12(VSS) U54.T1(VSS) U54.T3(VSS) U54.T5(VSS) U54.T8(VSS) U54.T10(VSS) U54.T12(VSS) U54.V1(VSS) U54.V5(VSS) U54.V8(VSS) U54.V12(VSS) U54.W2(VSS) U54.W4(VSS) U54.W9(VSS) U54.W11(VSS) U54.Y1(VSS) U54.Y5(VSS) U54.Y8(VSS) U54.Y12(VSS) U71.A3(VSS) U71.A10(VSS) U71.AB3(VSS) U71.AB5(VSS) U71.AB8(VSS) U71.AB10(VSS) U71.C1(VSS) U71.C5(VSS) U71.C8(VSS) U71.C12(VSS) U71.D2(VSS) U71.D4(VSS) U71.D9(VSS) U71.D11(VSS) U71.E1(VSS) U71.E5(VSS) U71.E8(VSS) U71.E12(VSS) U71.G1(VSS) U71.G3(VSS) U71.G5(VSS) U71.G8(VSS) U71.G10(VSS) U71.G12(VSS) U71.J1(VSS) U71.J3(VSS) U71.J10(VSS) U71.J12(VSS) U71.K2(VSS) U71.K4(VSS) U71.K9(VSS) U71.K11(VSS) U71.N2(VSS) U71.N4(VSS) U71.N9(VSS) U71.N11(VSS) U71.P1(VSS) U71.P3(VSS) U71.P10(VSS) U71.P12(VSS) U71.T1(VSS) U71.T3(VSS) U71.T5(VSS) U71.T8(VSS) U71.T10(VSS) U71.T12(VSS) U71.V1(VSS) U71.V5(VSS) U71.V8(VSS) U71.V12(VSS) U71.W2(VSS) U71.W4(VSS) U71.W9(VSS) U71.W11(VSS) U71.Y1(VSS) U71.Y5(VSS) U71.Y8(VSS) U71.Y12(VSS) ; also on sheet 11 12 16 17 18 20 21 22 23 24 25 26 27 28 29 30 31 32 33 34 35 36 37 38 39 40 41 42 43 44 45 46 47 48 49 50 51 52 53 54 55 56 57 58 59 60 61 62 63 64 65 66 67 68 69 70 71 72 73 76 77 78 79 81 82 83 84
VDD1_DDR_1V8: C228.1 C311.1 C783.1 C787.1 C791.1 C814.1 C817.1 C872.1 C884.1 C912.1 C934.1 C936.1 C952.1 C954.1 C979.1 C1024.1 C1033.1 C1066.1 C1068.1 C1085.1 C1090.1 C1092.1 U54.F1(VDD1) U54.F12(VDD1) U54.G4(VDD1) U54.G9(VDD1) U54.T4(VDD1) U54.T9(VDD1) U54.U1(VDD1) U54.U12(VDD1) U71.F1(VDD1) U71.F12(VDD1) U71.G4(VDD1) U71.G9(VDD1) U71.T4(VDD1) U71.T9(VDD1) U71.U1(VDD1) U71.U12(VDD1) ; also on sheet 54 75
VDD_DDR_1V1: C227.1 C229.1 C230.1 C240.1 C275.1 C309.1 C310.1 C312.1 C784.1 C792.1 C793.1 C794.1 C795.1 C806.1 C811.1 C838.1 C839.1 C846.1 C877.1 C890.1 C897.1 C913.1 C914.1 C915.1 C933.1 C935.1 C953.1 C955.1 C978.1 C981.1 C982.1 C1000.1 C1010.1 C1037.1 C1044.1 C1051.1 C1053.1 C1054.1 C1069.1 C1074.1 C1081.1 C1083.1 C1084.1 C1091.1 R978.1 R1012.1 R1019.1 R1020.1 R1040.1 R1041.1 R1054.1 R1121.1 U54.A4(VDD2) U54.A9(VDD2) U54.AA3(VDDQ) U54.AA5(VDDQ) U54.AA8(VDDQ) U54.AA10(VDDQ) U54.AB4(VDD2) U54.AB9(VDD2) U54.B3(VDDQ) U54.B5(VDDQ) U54.B8(VDDQ) U54.B10(VDDQ) U54.D1(VDDQ) U54.D5(VDDQ) U54.D8(VDDQ) U54.D12(VDDQ) U54.F3(VDDQ) U54.F5(VDD2) U54.F8(VDD2) U54.F10(VDDQ) U54.H1(VDD2) U54.H5(VDD2) U54.H8(VDD2) U54.H12(VDD2) U54.K1(VDD2) U54.K3(VDD2) U54.K10(VDD2) U54.K12(VDD2) U54.N1(VDD2) U54.N3(VDD2) U54.N10(VDD2) U54.N12(VDD2) U54.R1(VDD2) U54.R5(VDD2) U54.R8(VDD2) U54.R12(VDD2) U54.U3(VDDQ) U54.U5(VDD2) U54.U8(VDD2) U54.U10(VDDQ) U54.W1(VDDQ) U54.W5(VDDQ) U54.W8(VDDQ) U54.W12(VDDQ) U71.A4(VDD2) U71.A9(VDD2) U71.AA3(VDDQ) U71.AA5(VDDQ) U71.AA8(VDDQ) U71.AA10(VDDQ) U71.AB4(VDD2) U71.AB9(VDD2) U71.B3(VDDQ) U71.B5(VDDQ) U71.B8(VDDQ) U71.B10(VDDQ) U71.D1(VDDQ) U71.D5(VDDQ) U71.D8(VDDQ) U71.D12(VDDQ) U71.F3(VDDQ) U71.F5(VDD2) U71.F8(VDD2) U71.F10(VDDQ) U71.H1(VDD2) U71.H5(VDD2) U71.H8(VDD2) U71.H12(VDD2) U71.K1(VDD2) U71.K3(VDD2) U71.K10(VDD2) U71.K12(VDD2) U71.N1(VDD2) U71.N3(VDD2) U71.N10(VDD2) U71.N12(VDD2) U71.R1(VDD2) U71.R5(VDD2) U71.R8(VDD2) U71.R12(VDD2) U71.U3(VDDQ) U71.U5(VDD2) U71.U8(VDD2) U71.U10(VDDQ) U71.W1(VDDQ) U71.W5(VDDQ) U71.W8(VDDQ) U71.W12(VDDQ) ; also on sheet 26 28 69 74 75
C_DP0_TX0_N: C45.1 U59.AJ21(SERDES4_TX0_N)
C_DP0_TX0_P: C44.1 U59.AJ22(SERDES4_TX0_P)
C_DP0_TX1_N: C38.1 U59.AM18(SERDES4_TX1_N)
C_DP0_TX1_P: C37.1 U59.AM19(SERDES4_TX1_P)
C_DP0_TX2_N: C47.1 U59.AN20(SERDES4_TX2_N)
C_DP0_TX2_P: C46.1 U59.AN21(SERDES4_TX2_P)
C_DP0_TX3_N: C40.1 U59.AL22(SERDES4_TX3_N)
C_DP0_TX3_P: C39.1 U59.AL23(SERDES4_TX3_P)
C_PCIE0_TX0_N: C627.1 U59.AK11(SERDES1_TX0_N)
C_PCIE0_TX0_P: C628.1 U59.AK12(SERDES1_TX0_P)
C_PCIE0_TX1_N: C625.1 U59.AM9(SERDES1_TX1_N)
C_PCIE0_TX1_P: C626.1 U59.AM10(SERDES1_TX1_P)
C_PCIE0_TX2_N: C623.1 U59.AK8(SERDES1_TX2_N)
C_PCIE0_TX2_P: C624.1 U59.AK9(SERDES1_TX2_P)
C_PCIE0_TX3_N: C621.1 U59.AJ9(SERDES1_TX3_N)
C_PCIE0_TX3_P: C622.1 U59.AJ10(SERDES1_TX3_P)
DDR0_CA0: U54.H2(CA0_A) U54.R2(CA0_B) U59.AA3(DDR0_CA0)
DDR0_CA1: U54.J2(CA1_A) U54.P2(CA1_B) U59.Y4(DDR0_CA1)
DDR0_CA2: U54.H9(CA2_A) U54.R9(CA2_B) U59.AA4(DDR0_CA2)
DDR0_CA3: U54.H10(CA3_A) U54.R10(CA3_B) U59.AB3(DDR0_CA3)
DDR0_CA4: U54.H11(CA4_A) U54.R11(CA4_B) U59.Y3(DDR0_CA4)
DDR0_CA5: U54.J11(CA5_A) U54.P11(CA5_B) U59.AB5(DDR0_CA5)
DDR0_CAL0: R946.1 U59.R7(DDR0_CAL0)
DDR0_CK_C: U54.J9(CK_C_A) U54.P9(CK_C_B) U59.Y2(DDR0_CKN)
DDR0_CK_T: U54.J8(CK_T_A) U54.P8(CK_T_B) U59.AA1(DDR0_CKP)
DDR0_CKE0: U54.J4(CKE0_A) U54.P4(CKE0_B) U59.AB6(DDR0_CKE0)
DDR0_CKE1: U54.J5(CKE1_A) U54.P5(CKE1_B) U59.AB7(DDR0_CKE1)
DDR0_CSN0_0: U54.H4(CS0_A) U59.AA6(DDR0_CSN0_0)
DDR0_CSN0_1: U54.R4(CS0_B) U59.Y5(DDR0_CSN0_1)
DDR0_CSN1_0: U54.H3(CS1_A) U59.Y7(DDR0_CSN1_0)
DDR0_CSN1_1: U54.R3(CS1_B) U59.AA7(DDR0_CSN1_1)
DDR0_DM0_DBI0#: U54.C3(DMI0_A) U59.U6(DDR0_DM0)
DDR0_DM1_DBI1#: U54.C10(DMI1_A) U59.V2(DDR0_DM1)
DDR0_DM2_DBI2#: U54.Y3(DMI0_B) U59.AE2(DDR0_DM2)
DDR0_DM3_DBI3#: U54.Y10(DMI1_B) U59.AF6(DDR0_DM3)
DDR0_DQ0: U54.B2(DQ0_A) U59.R5(DDR0_DQ0)
DDR0_DQ1: U54.C2(DQ1_A) U59.R4(DDR0_DQ1)
DDR0_DQ2: U54.E2(DQ2_A) U59.R2(DDR0_DQ2)
DDR0_DQ3: U54.F2(DQ3_A) U59.T4(DDR0_DQ3)
DDR0_DQ4: U54.F4(DQ4_A) U59.U5(DDR0_DQ4)
DDR0_DQ5: U54.E4(DQ5_A) U59.T3(DDR0_DQ5)
DDR0_DQ6: U54.C4(DQ6_A) U59.T6(DDR0_DQ6)
DDR0_DQ7: U54.B4(DQ7_A) U59.T7(DDR0_DQ7)
DDR0_DQ8: U54.B11(DQ8_A) U59.V4(DDR0_DQ8)
DDR0_DQ9: U54.C11(DQ9_A) U59.V7(DDR0_DQ9)
DDR0_DQ10: U54.E11(DQ10_A) U59.W3(DDR0_DQ10)
DDR0_DQ11: U54.F11(DQ11_A) U59.V5(DDR0_DQ11)
DDR0_DQ12: U54.F9(DQ12_A) U59.W6(DDR0_DQ12)
DDR0_DQ13: U54.E9(DQ13_A) U59.U2(DDR0_DQ13)
DDR0_DQ14: U54.C9(DQ14_A) U59.W4(DDR0_DQ14)
DDR0_DQ15: U54.B9(DQ15_A) U59.U3(DDR0_DQ15)
DDR0_DQ16: U54.AA2(DQ0_B) U59.AD5(DDR0_DQ16)
DDR0_DQ17: U54.Y2(DQ1_B) U59.AC3(DDR0_DQ17)
DDR0_DQ18: U54.V2(DQ2_B) U59.AE3(DDR0_DQ18)
DDR0_DQ19: U54.U2(DQ3_B) U59.AB2(DDR0_DQ19)
DDR0_DQ20: U54.U4(DQ4_B) U59.AC4(DDR0_DQ20)
DDR0_DQ21: U54.V4(DQ5_B) U59.AD2(DDR0_DQ21)
DDR0_DQ22: U54.Y4(DQ6_B) U59.AC6(DDR0_DQ22)
DDR0_DQ23: U54.AA4(DQ7_B) U59.AD4(DDR0_DQ23)
DDR0_DQ24: U54.AA11(DQ8_B) U59.AG4(DDR0_DQ24)
DDR0_DQ25: U54.Y11(DQ9_B) U59.AG2(DDR0_DQ25)
DDR0_DQ26: U54.V11(DQ10_B) U59.AF3(DDR0_DQ26)
DDR0_DQ27: U54.U11(DQ11_B) U59.AE5(DDR0_DQ27)
DDR0_DQ28: U54.U9(DQ12_B) U59.AE6(DDR0_DQ28)
DDR0_DQ29: U54.V9(DQ13_B) U59.AG5(DDR0_DQ29)
DDR0_DQ30: U54.Y9(DQ14_B) U59.AF4(DDR0_DQ30)
DDR0_DQ31: U54.AA9(DQ15_B) U59.AH6(DDR0_DQ31)
DDR0_DQS0_N: U54.E3(DQS0_C_A) U59.T1(DDR0_DQS0N)
DDR0_DQS0_P: U54.D3(DQS0_T_A) U59.R1(DDR0_DQS0P)
DDR0_DQS1_N: U54.E10(DQS1_C_A) U59.W1(DDR0_DQS1N)
DDR0_DQS1_P: U54.D10(DQS1_T_A) U59.V1(DDR0_DQS1P)
DDR0_DQS2_N: U54.V3(DQS0_C_B) U59.AC1(DDR0_DQS2N)
DDR0_DQS2_P: U54.W3(DQS0_T_B) U59.AD1(DDR0_DQS2P)
DDR0_DQS3_N: U54.V10(DQS1_C_B) U59.AF1(DDR0_DQS3N)
DDR0_DQS3_P: U54.W10(DQS1_T_B) U59.AG1(DDR0_DQS3P)
DDR0_ODT_CA_A: R998.1 R1012.2 U54.G2(ODT_CA_A)
DDR0_ODT_CA_B: R970.1 R978.2 U54.T2(ODT_CA_B)
DDR0_RET: R378.1 U59.AC7(DDR0_RET)
DDR0_RST#: R965.1 U54.T11(RESET_N) U59.W7(DDR0_RESETN)
DDR0_ZQ0: R1019.2 U54.A5(ZQ0)
DDR0_ZQ1: R1020.2 U54.A8(ZQ1)
DDR1_CA0: U59.J4(DDR1_CA0) U71.H2(CA0_A) U71.R2(CA0_B)
DDR1_CA1: U59.H3(DDR1_CA1) U71.J2(CA1_A) U71.P2(CA1_B)
DDR1_CA2: U59.G2(DDR1_CA2) U71.H9(CA2_A) U71.R9(CA2_B)
DDR1_CA3: U59.J3(DDR1_CA3) U71.H10(CA3_A) U71.R10(CA3_B)
DDR1_CA4: U59.G3(DDR1_CA4) U71.H11(CA4_A) U71.R11(CA4_B)
DDR1_CA5: U59.H4(DDR1_CA5) U71.J11(CA5_A) U71.P11(CA5_B)
DDR1_CAL0: R396.1 U59.F8(DDR1_CAL0)
DDR1_CK_C: U59.H1(DDR1_CKN) U71.J9(CK_C_A) U71.P9(CK_C_B)
DDR1_CK_T: U59.J2(DDR1_CKP) U71.J8(CK_T_A) U71.P8(CK_T_B)
DDR1_CKE0: U59.E7(DDR1_CKE0) U71.J4(CKE0_A) U71.P4(CKE0_B)
DDR1_CKE1: U59.H6(DDR1_CKE1) U71.J5(CKE1_A) U71.P5(CKE1_B)
DDR1_CSN0_0: U59.G6(DDR1_CSN0_0) U71.H4(CS0_A)
DDR1_CSN0_1: U59.G7(DDR1_CSN0_1) U71.R4(CS0_B)
DDR1_CSN1_0: U59.H7(DDR1_CSN1_0) U71.H3(CS1_A)
DDR1_CSN1_1: U59.F6(DDR1_CSN1_1) U71.R3(CS1_B)
DDR1_DM0_DBI0#: U59.A3(DDR1_DM0) U71.C3(DMI0_A)
DDR1_DM1_DBI1#: U59.F3(DDR1_DM1) U71.C10(DMI1_A)
DDR1_DM2_DBI2#: U59.L2(DDR1_DM2) U71.Y3(DMI0_B)
DDR1_DM3_DBI3#: U59.P2(DDR1_DM3) U71.Y10(DMI1_B)
DDR1_DQ0: U59.A6(DDR1_DQ0) U71.B2(DQ0_A)
DDR1_DQ1: U59.C6(DDR1_DQ1) U71.C2(DQ1_A)
DDR1_DQ2: U59.A5(DDR1_DQ2) U71.E2(DQ2_A)
DDR1_DQ3: U59.C4(DDR1_DQ3) U71.F2(DQ3_A)
DDR1_DQ4: U59.B4(DDR1_DQ4) U71.F4(DQ4_A)
DDR1_DQ5: U59.B2(DDR1_DQ5) U71.E4(DQ5_A)
DDR1_DQ6: U59.C3(DDR1_DQ6) U71.C4(DQ6_A)
DDR1_DQ7: U59.B5(DDR1_DQ7) U71.B4(DQ7_A)
DDR1_DQ8: U59.E5(DDR1_DQ8) U71.B11(DQ8_A)
DDR1_DQ9: U59.D2(DDR1_DQ9) U71.C11(DQ9_A)
DDR1_DQ10: U59.E2(DDR1_DQ10) U71.E11(DQ10_A)
DDR1_DQ11: U59.F4(DDR1_DQ11) U71.F11(DQ11_A)
DDR1_DQ12: U59.D6(DDR1_DQ12) U71.F9(DQ12_A)
DDR1_DQ13: U59.E4(DDR1_DQ13) U71.E9(DQ13_A)
DDR1_DQ14: U59.D3(DDR1_DQ14) U71.C9(DQ14_A)
DDR1_DQ15: U59.D5(DDR1_DQ15) U71.B9(DQ15_A)
DDR1_DQ16: U59.M3(DDR1_DQ16) U71.AA2(DQ0_B)
DDR1_DQ17: U59.K4(DDR1_DQ17) U71.Y2(DQ1_B)
DDR1_DQ18: U59.M2(DDR1_DQ18) U71.V2(DQ2_B)
DDR1_DQ19: U59.L5(DDR1_DQ19) U71.U2(DQ3_B)
DDR1_DQ20: U59.J5(DDR1_DQ20) U71.U4(DQ4_B)
DDR1_DQ21: U59.K3(DDR1_DQ21) U71.V4(DQ5_B)
DDR1_DQ22: U59.L4(DDR1_DQ22) U71.Y4(DQ6_B)
DDR1_DQ23: U59.K6(DDR1_DQ23) U71.AA4(DQ7_B)
DDR1_DQ24: U59.N6(DDR1_DQ24) U71.AA11(DQ8_B)
DDR1_DQ25: U59.P4(DDR1_DQ25) U71.Y11(DQ9_B)
DDR1_DQ26: U59.N3(DDR1_DQ26) U71.V11(DQ10_B)
DDR1_DQ27: U59.M5(DDR1_DQ27) U71.U11(DQ11_B)
DDR1_DQ28: U59.M6(DDR1_DQ28) U71.U9(DQ12_B)
DDR1_DQ29: U59.P5(DDR1_DQ29) U71.V9(DQ13_B)
DDR1_DQ30: U59.N4(DDR1_DQ30) U71.Y9(DQ14_B)
DDR1_DQ31: U59.P6(DDR1_DQ31) U71.AA9(DQ15_B)
DDR1_DQS0_N: U59.C1(DDR1_DQS0N) U71.E3(DQS0_C_A)
DDR1_DQS0_P: U59.B1(DDR1_DQS0P) U71.D3(DQS0_T_A)
DDR1_DQS1_N: U59.F1(DDR1_DQS1N) U71.E10(DQS1_C_A)
DDR1_DQS1_P: U59.E1(DDR1_DQS1P) U71.D10(DQS1_T_A)
DDR1_DQS2_N: U59.K1(DDR1_DQS2N) U71.V3(DQS0_C_B)
DDR1_DQS2_P: U59.L1(DDR1_DQS2P) U71.W3(DQS0_T_B)
DDR1_DQS3_N: U59.N1(DDR1_DQS3N) U71.V10(DQS1_C_B)
DDR1_DQS3_P: U59.P1(DDR1_DQS3P) U71.W10(DQS1_T_B)
DDR1_ODT_CA_A: R1054.2 R1064.1 U71.G2(ODT_CA_A)
DDR1_ODT_CA_B: R1121.2 R1127.1 U71.T2(ODT_CA_B)
DDR1_RET: R404.1 U59.G8(DDR1_RET)
DDR1_RST#: R1120.1 U59.G5(DDR1_RESETN) U71.T11(RESET_N)
DDR1_ZQ0: R1041.2 U71.A5(ZQ0)
DDR1_ZQ1: R1040.2 U71.A8(ZQ1)
DP0_TX0_N: C45.2 ; also on sheet 57
DP0_TX0_P: C44.2 ; also on sheet 57
DP0_TX1_N: C38.2 ; also on sheet 57
DP0_TX1_P: C37.2 ; also on sheet 57
DP0_TX2_N: C47.2 ; also on sheet 57
DP0_TX2_P: C46.2 ; also on sheet 57
DP0_TX3_N: C40.2 ; also on sheet 57
DP0_TX3_P: C39.2 ; also on sheet 57
EN_DDR_RET_1V1: R378.2 R404.2 ; also on sheet 69 72
PCIE0_RX0_N: U59.AL10(SERDES1_RX0_N) ; also on sheet 59
PCIE0_RX0_P: U59.AL11(SERDES1_RX0_P) ; also on sheet 59
PCIE0_RX1_N: U59.AN8(SERDES1_RX1_N) ; also on sheet 59
PCIE0_RX1_P: U59.AN9(SERDES1_RX1_P) ; also on sheet 59
PCIE0_RX2_N: U59.AM6(SERDES1_RX2_N) ; also on sheet 59
PCIE0_RX2_P: U59.AM7(SERDES1_RX2_P) ; also on sheet 59
PCIE0_RX3_N: U59.AL7(SERDES1_RX3_N) ; also on sheet 59
PCIE0_RX3_P: U59.AL8(SERDES1_RX3_P) ; also on sheet 59
PCIE0_TX0_N: C627.2 ; also on sheet 59
PCIE0_TX0_P: C628.2 ; also on sheet 59
PCIE0_TX1_N: C625.2 ; also on sheet 59
PCIE0_TX1_P: C626.2 ; also on sheet 59
PCIE0_TX2_N: C623.2 ; also on sheet 59
PCIE0_TX2_P: C624.2 ; also on sheet 59
PCIE0_TX3_N: C621.2 ; also on sheet 59
PCIE0_TX3_P: C622.2 ; also on sheet 59
PCIE_REFCLK1_OUT_N: R859.2 U59.AJ13(PCIE_REFCLK0_N_OUT)
PCIE_REFCLK1_OUT_P: R860.2 U59.AJ12(PCIE_REFCLK0_P_OUT)
PCIE_REFCLK2_OUT_N: TP10124.1(TP) U59.AH11(PCIE_REFCLK2_N_OUT)
PCIE_REFCLK2_OUT_P: TP10123.1(TP) U59.AH10(PCIE_REFCLK2_P_OUT)
R_SOC_SERDES1_REFCLK_N: R869.2 U59.AN5(SERDES1_REFCLK_N)
R_SOC_SERDES1_REFCLK_P: R870.2 U59.AN6(SERDES1_REFCLK_P)
R_SOC_SERDES4_REFCLK_N: R174.2 U59.AK21(SERDES4_REFCLK_N)
R_SOC_SERDES4_REFCLK_P: R175.2 U59.AK20(SERDES4_REFCLK_P)
SERDES1_REXT: R945.1 U59.AH9(SERDES1_REXT)
SERDES4_REXT: R938.1 U59.AH23(SERDES4_REXT)
SOC_SERDES1_REFCLK_N: R859.1 R861.1 R869.1 ; also on sheet 59
SOC_SERDES1_REFCLK_P: R860.1 R862.1 R870.1 ; also on sheet 59
SOC_SERDES4_REFCLK_N: R174.1 ; also on sheet 33
SOC_SERDES4_REFCLK_P: R175.1 ; also on sheet 33

Not connected (* = marked no-connect by the designer): U54 A1(DNU1) A2(DNU2) A11(DNU3) A12(DNU4) AA1(DNU7) AA12(DNU8) AB1(DNU9) AB2(DNU10) AB11(DNU11) AB12(DNU12) B1(DNU5) B12(DNU6) G11(NC1) K5(NC2) K8(NC3) N5(NC4) N8(NC5); U59 AK23(SERDES4_RX2_N)* AK24(SERDES4_RX2_P)* AL19(SERDES4_RX1_N)* AL20(SERDES4_RX1_P)* AM21(SERDES4_RX3_N)* AM22(SERDES4_RX3_P)* AN17(SERDES4_RX0_N)* AN18(SERDES4_RX0_P)*; U71 A1(DNU1) A2(DNU2) A11(DNU3) A12(DNU4) AA1(DNU7) AA12(DNU8) AB1(DNU9) AB2(DNU10) AB11(DNU11) AB12(DNU12) B1(DNU5) B12(DNU6) G11(NC1) K5(NC2) K8(NC3) N5(NC4) N8(NC5)

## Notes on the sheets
sheet 13
- SERDES1
- x4LANE PCIe0 INTERFACE
- SERDES4
- DISPLAY PORT 0
sheet 14
- LPDDR4
sheet 15
- LPDDR4
